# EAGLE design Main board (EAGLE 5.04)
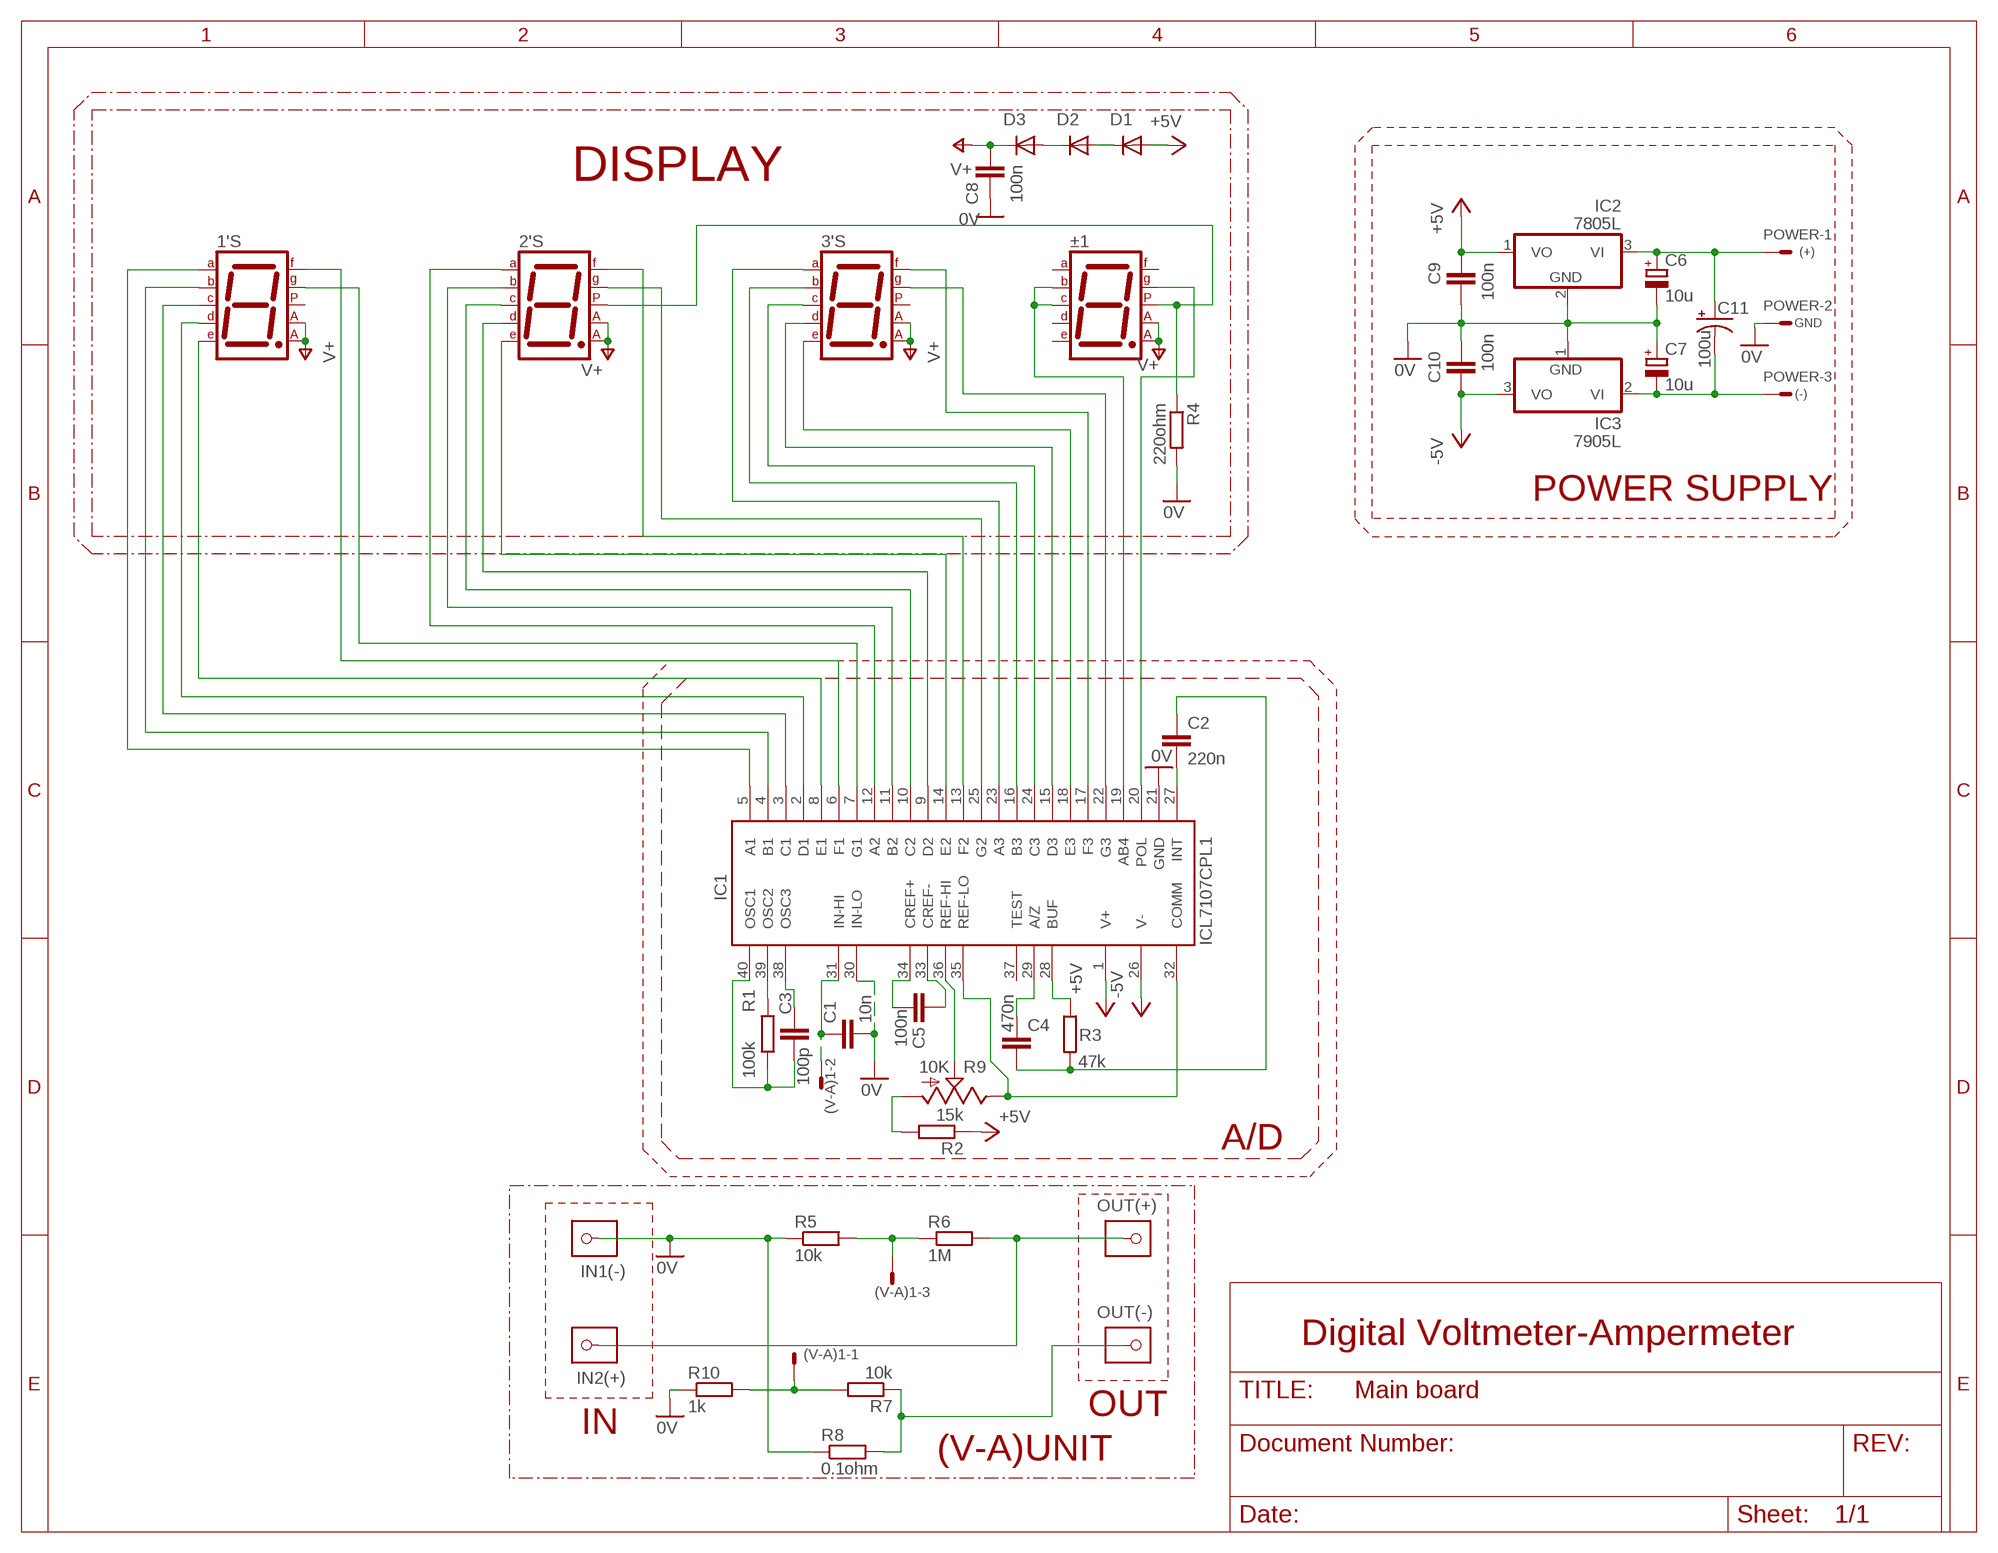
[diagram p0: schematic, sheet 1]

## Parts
1'S  7SEG-CA  [7SEG-13]
2'S  7SEG-CA  [7SEG-13]
3'S  7SEG-CA  [7SEG-13]
(V-A)1  22-27-2031-03  [6410-03]
C1  10n  C-EU050-025X075  [C050-025X075]
C2  220n  C-EU050-025X075  [C050-025X075]
C3  100p  C-EU050-025X075  [C050-025X075]
C4  470n  C-EU050-025X075  [C050-025X075]
C5  100n  C-EU050-025X075  [C050-025X075]
C6  10u  CPOL-EUE2.5-6  [E2,5-6]
C7  10u  CPOL-EUE2.5-6  [E2,5-6]
C8  100n  C-EU050-025X075  [C050-025X075]
C9  100n  C-EU050-025X075  [C050-025X075]
C10  100n  C-EU050-025X075  [C050-025X075]
C11  100u  CPOL-USE5-8.5  [E5-8,5]
D1  1N4148DO35-7  [DO35-7]
D2  1N4148DO35-7  [DO35-7]
D3  1N4148DO35-7  [DO35-7]
IC1  ICL7107CPL1  [DIL40]
IC2  7805L  [TO92]
IC3  7905L  [TO92]
IN1(-)  PINHEAD  [PINFOOT]
IN2(+)  PINHEAD  [PINFOOT]
OUT(+)  PINHEAD  [PINFOOT]
OUT(-)  PINHEAD  [PINFOOT]
POWER  22-27-2031-03  [6410-03]
R1  100k  R-EU_0207/10  [0207/10]
R2  15k  R-EU_0207/10  [0207/10]
R3  47k  R-EU_0207/10  [0207/10]
R4  220ohm  R-EU_0207/10  [0207/10]
R5  10k  R-EU_0207/10  [0207/10]
R6  1M  R-EU_0207/10  [0207/10]
R7  10k  R-EU_0207/10  [0207/10]
R8  0.1ohm  R-EU_0922/22  [0922/22]
R9  10K  TRIM_US-CA6V  [CA6V]
R10  1k  R-EU_0207/10  [0207/10]
±1  7SEG-CA  [7SEG-13]

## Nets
0V: C1.2 C6.- C7.+ C8.1 C9.1 C10.2 IC1.21(GND) IC1.30(IN-LO) IC2.2(GND) IC3.1(GND) IN1(-).P$1 POWER.2 R4.2 R5.1 R8.1 R10.1
+5V: C9.2 D1.A IC1.1(V+) IC2.1(VO) R2.1
-5V: C10.1 IC1.26(V-) IC3.3(VO)
N$1: 2'S.5(DP) R4.1 ±1.5(DP)
N$2: IC1.39(OSC2) R1.2
N$3: C7.- C11.- IC3.2(VI) POWER.3
N$4: C6.+ C11.+ IC2.3(VI) POWER.1
N$5: C3.1 IC1.38(OSC3)
N$6: (V-A)1.3 R5.2 R6.1
N$7: OUT(-).P$1 R7.1 R8.2
N$8: (V-A)1.1 R7.2 R10.2
N$9: C4.1 IC1.29(A/Z)
N$10: IC1.28(BUF) R3.1
N$11: C2.1 C4.2 R3.2
N$12: C2.2 IC1.27(INT)
N$13: C5.2 IC1.33(CREF-)
N$14: D2.C D3.A
N$15: D1.C D2.A
N$16: C5.1 IC1.34(CREF+)
N$17: C3.2 IC1.40(OSC1) R1.1
N$20: IC1.36(REF-HI) R9.S
N$21: IC1.32(COMM) IC1.35(REF-LO) R9.E
N$22: 3'S.10(G) IC1.22(G3)
N$23: 3'S.9(F) IC1.17(F3)
N$24: R2.2 R9.A
N$25: 3'S.1(E) IC1.18(E3)
N$26: 3'S.2(D) IC1.15(D3)
N$27: IC1.20(POL) ±1.10(G)
N$28: IC1.19(AB4) ±1.4(C) ±1.6(B)
N$29: 3'S.4(C) IC1.24(C3)
N$30: 3'S.6(B) IC1.16(B3)
N$31: 3'S.7(A) IC1.23(A3)
N$32: 2'S.10(G) IC1.25(G2)
N$33: 2'S.9(F) IC1.13(F2)
N$34: 2'S.1(E) IC1.14(E2)
N$35: 2'S.2(D) IC1.9(D2)
N$36: 2'S.4(C) IC1.10(C2)
N$37: 2'S.6(B) IC1.11(B2)
N$38: 2'S.7(A) IC1.12(A2)
N$39: 1'S.10(G) IC1.7(G1)
N$40: 1'S.9(F) IC1.6(F1)
N$41: 1'S.1(E) IC1.8(E1)
N$42: 1'S.2(D) IC1.2(D1)
N$43: 1'S.4(C) IC1.3(C1)
N$44: 1'S.6(B) IC1.4(B1)
N$45: 1'S.7(A) IC1.5(A1)
N$47: IN2(+).P$1 OUT(+).P$1 R6.2
N$48: (V-A)1.2 C1.1 IC1.31(IN-HI)
V+: 1'S.3(CA1) 1'S.8(CA2) 2'S.3(CA1) 2'S.8(CA2) 3'S.3(CA1) 3'S.8(CA2) C8.2 D3.C ±1.3(CA1) ±1.8(CA2)
Unconnected: 1'S.5(DP) 3'S.5(DP) IC1.37(TEST) ±1.1(E) ±1.2(D) ±1.7(A) ±1.9(F)

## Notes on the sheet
- DISPLAY
- (+)
- GND
- (-)
- POWER SUPPLY
- A/D
- Digital Voltmeter-Ampermeter
- OUT
- IN
- (V-A)UNIT

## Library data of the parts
1'S 2'S 3'S ±1 = special:7SEG-CA: 7-segment DISPLAY single anode, 13 mm
(V-A)1 POWER = con-molex:22-?-03: CONNECTOR wire to board 2.54 mm (.1 inch) pitch header
C1-C5 C8-C10 = resistor:C-EU: CAPACITOR, European symbol
C6 C7 = resistor:CPOL-EU: POLARIZED CAPACITOR, European symbol
C11 = rcl:CPOL-US: POLARIZED CAPACITOR, American symbol
D1-D3 = diode:1N4148: DIODE
IC1 = maxim-3:ICL7107CPL: LED DRIVER
IC2 = linear:78*: Positive VOLTAGE REGULATOR Source: http://cache.national.com/ds/LM/LM78L05.pdf http://www.fairchildsemi.com/ds/LM/LM7805.pdf
IC3 = linear:79*: Negative VOLTAGE REGULATOR
IN1(-) IN2(+) OUT(+) OUT(-) = my lib:PINHEAD
R1-R8 R10 = resistor:R-EU_: RESISTOR, European symbol
R9 = pot:TRIM_US-: POTENTIOMETER

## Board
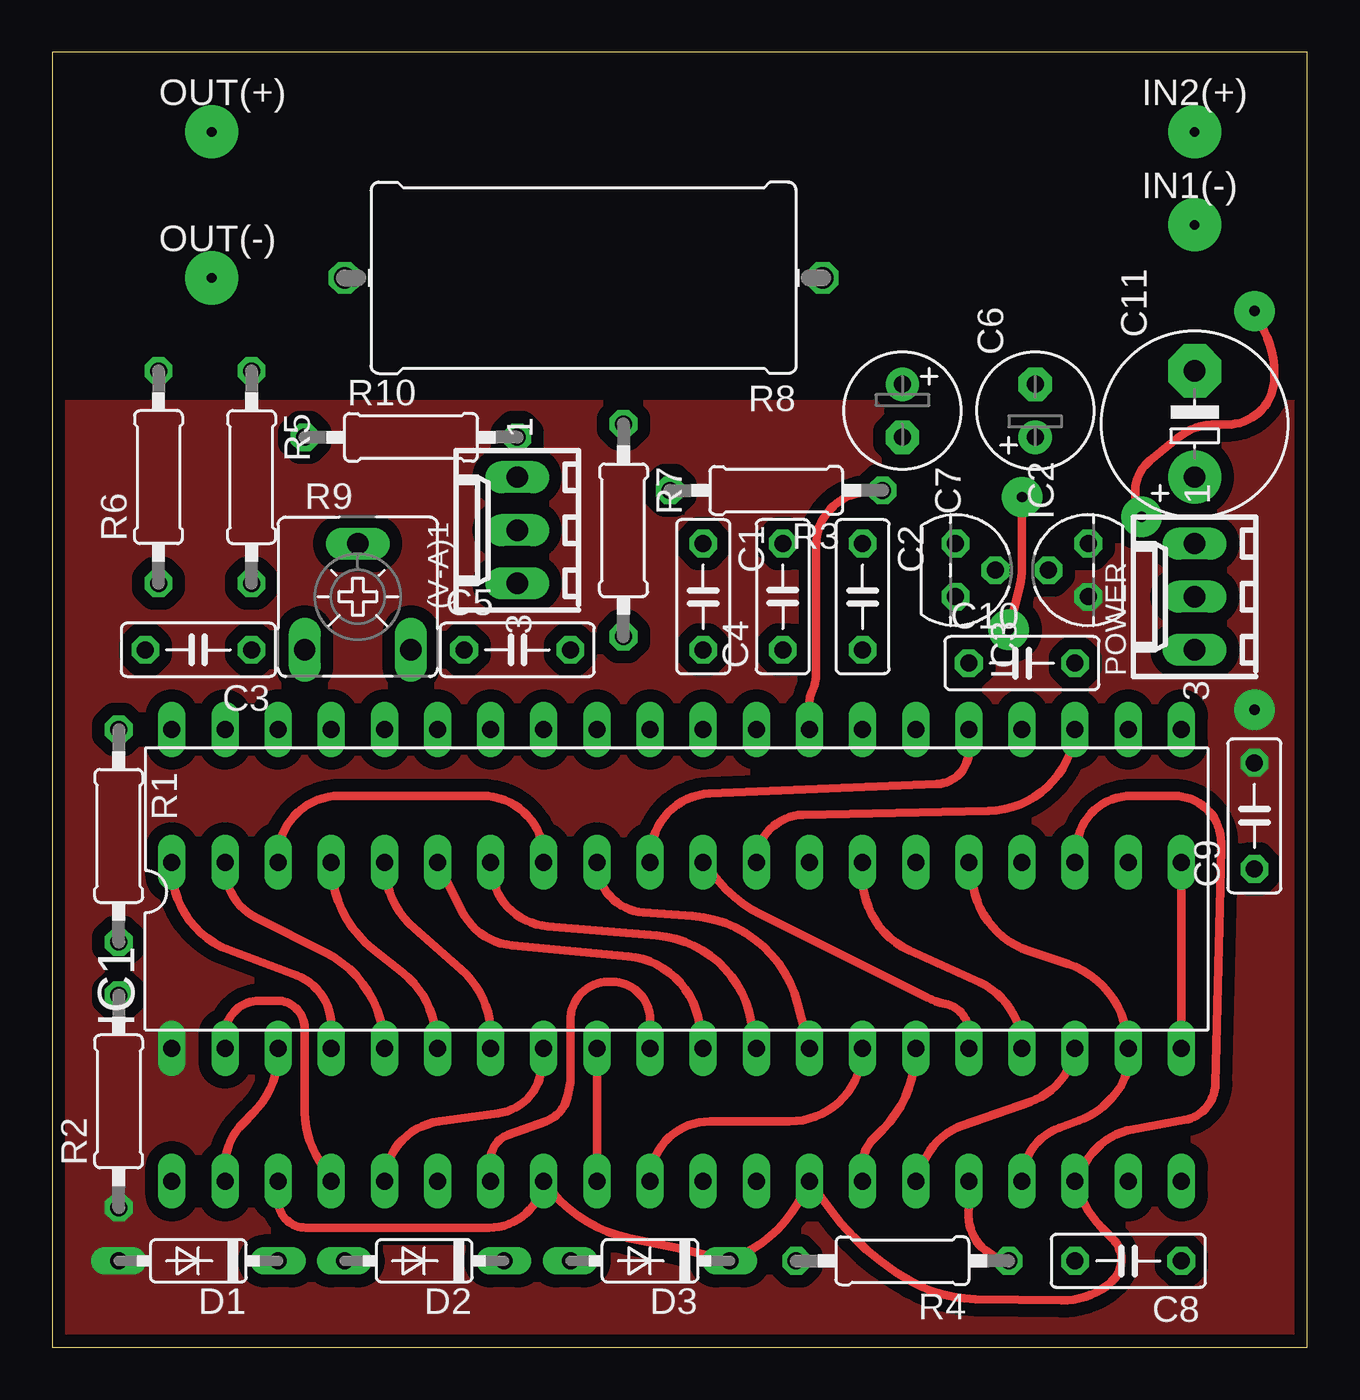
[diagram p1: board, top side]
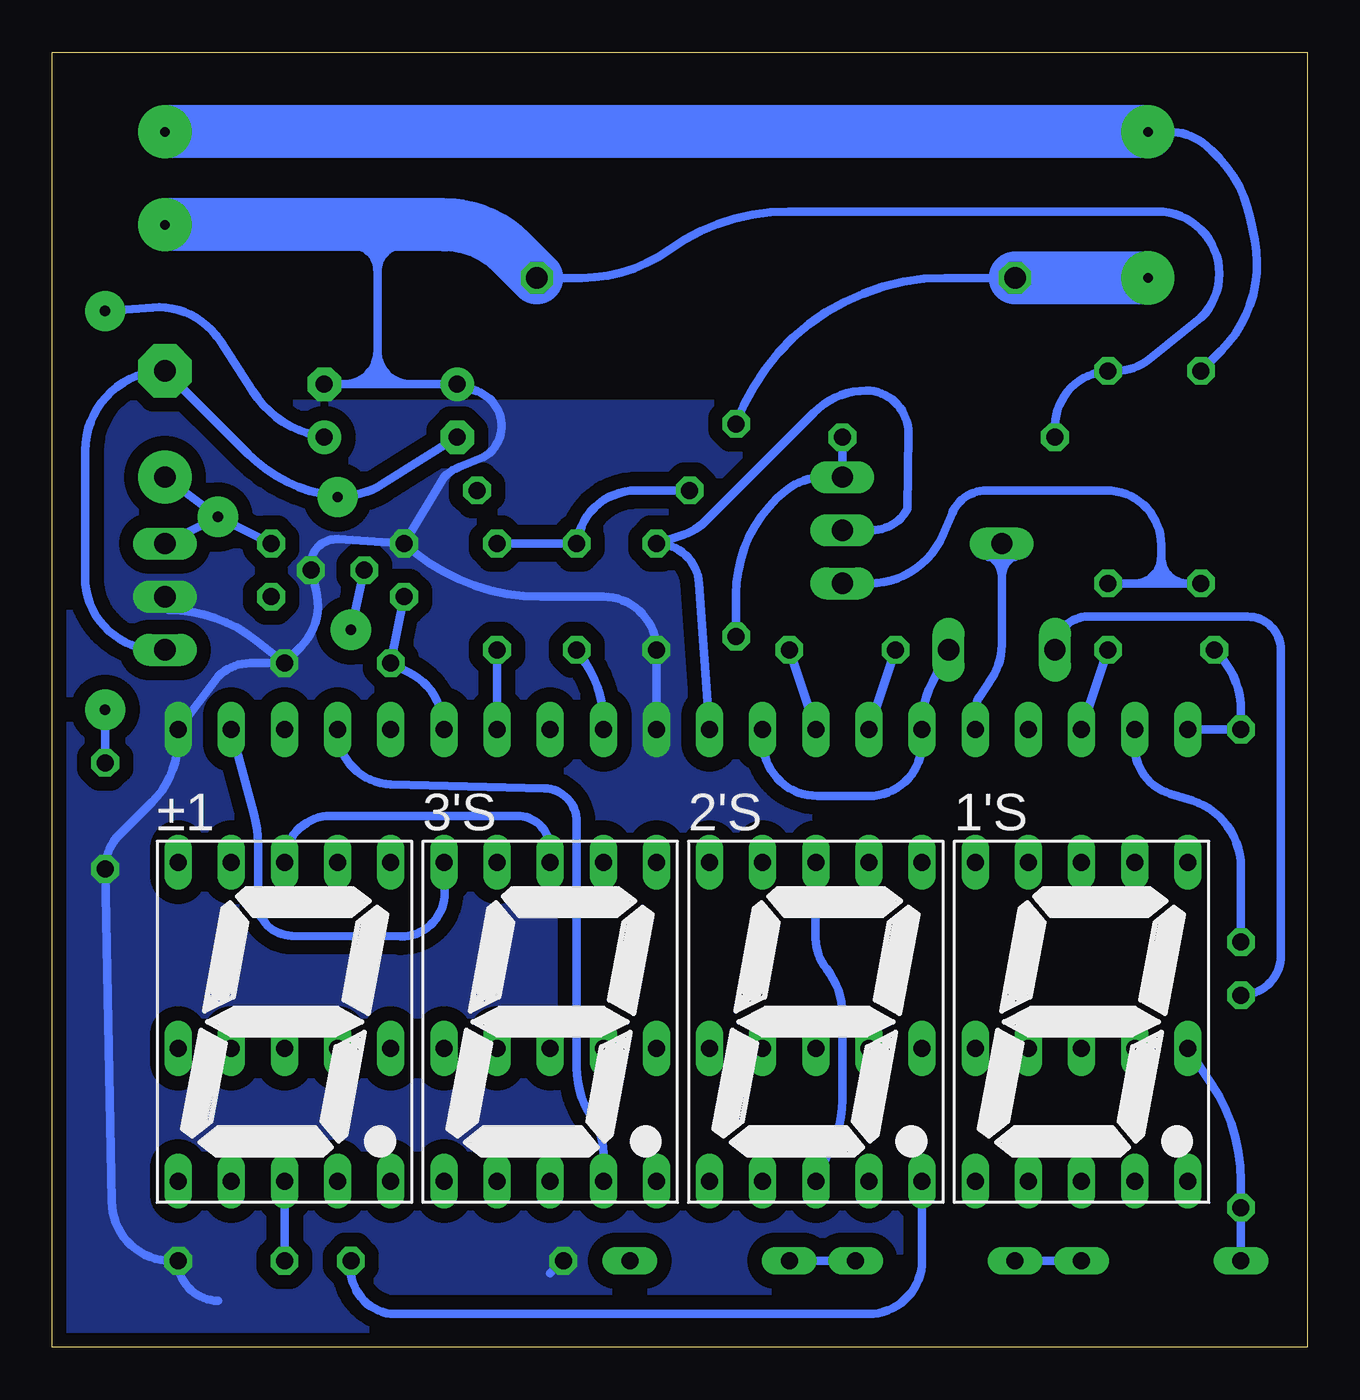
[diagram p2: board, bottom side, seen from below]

Size 59.99 x 61.9 mm. Coordinates in mm from the lower left corner, seen from the top.
Outline: 0,0 59.99,0 59.99,61.9 0,61.9 0,0
Copper layers (1*16): Top 0.035mm / dielectric 1.5mm / Bottom 0.035mm
Design rules "default *": minimum track width 16mil, minimum drill 10mil, track to track 10mil, track to pad 10mil, pad to pad 10mil, via to via 10mil, smd to smd 8mil, copper to edge 20mil, drill to drill 10mil, minimum pad ring 10mil, minimum via ring 8mil, stop-mask expansion 4mil, vias tented up to drill 0mil, thermal gap 10mil

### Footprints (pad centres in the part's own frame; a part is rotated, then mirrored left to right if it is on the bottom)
7SEG-13 = drill 0.813 long: 1 -5.08,-7.62; 2 -2.54,-7.62; 3 0,-7.62; 4 2.54,-7.62; 5 5.08,-7.62; 6 5.08,7.62; 7 2.54,7.62; 8 0,7.62; 9 -2.54,7.62; 10 -5.08,7.62
6410-03 = drill 1.016 long: 1 2.54,0; 2 0,0; 3 -2.54,0
C050-025X075 = drill 0.813 octagon: 1 -2.54,0; 2 2.54,0
E2,5-6 = drill 0.813 pad 1.6 round: + -1.27,0 | drill 0.813 pad 1.6 octagon: - 1.27,0
E5-8,5 = drill 1.016 pad 2.54 round: + -2.54,0 | drill 1.016 pad 2.54 octagon: - 2.54,0
DO35-7 = drill 0.813 long: A 3.81,0; C -3.81,0
DIL40 = drill 0.813 long: 1 -24.13,-7.62; 2 -21.59,-7.62; 3 -19.05,-7.62; 4 -16.51,-7.62; 5 -13.97,-7.62; 6 -11.43,-7.62; 7 -8.89,-7.62; 8 -6.35,-7.62; 9 -3.81,-7.62; 10 -1.27,-7.62; 11 1.27,-7.62; 12 3.81,-7.62; 13 6.35,-7.62; 14 8.89,-7.62; 15 11.43,-7.62; 16 13.97,-7.62; 17 16.51,-7.62; 18 19.05,-7.62; 19 21.59,-7.62; 20 24.13,-7.62; 21 24.13,7.62; 22 21.59,7.62; 23 19.05,7.62; 24 16.51,7.62; 25 13.97,7.62; 26 11.43,7.62; 27 8.89,7.62; 28 6.35,7.62; 29 3.81,7.62; 30 1.27,7.62; 31 -1.27,7.62; 32 -3.81,7.62; 33 -6.35,7.62; 34 -8.89,7.62; 35 -11.43,7.62; 36 -13.97,7.62; 37 -16.51,7.62; 38 -19.05,7.62; 39 -21.59,7.62; 40 -24.13,7.62
TO92 = drill 0.813 octagon: 1 -1.27,0; 2 0,1.905; 3 1.27,0
PINFOOT = drill 0.457 pad 2.54 round: P$1 0,0
0207/10 = drill 0.813 octagon: 1 -5.08,0; 2 5.08,0
0922/22 = drill 1.016 octagon: 1 -11.43,0; 2 11.43,0
CA6V = drill 1.016 long: A -2.54,-2.54; E 2.54,-2.54; S 0,2.54

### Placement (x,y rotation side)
1'S  10.79,15.56 0 bottom
2'S  23.5,15.56 0 bottom
3'S  36.2,15.56 0 bottom
(V-A)1  22.23,39.05 90 top
C1  31.11,35.88 270 top
C2  38.73,35.88 270 top
C3  6.99,33.34 180 top
C4  34.92,35.88 90 top
C5  22.23,33.34 0 top
C6  46.99,44.77 90 top
C7  40.64,44.77 270 top
C8  51.44,4.13 180 top
C9  57.47,25.4 90 top
C10  46.35,32.7 0 top
C11  54.61,44.13 90 top
D1  6.99,4.13 180 top
D2  17.78,4.13 180 top
D3  28.57,4.13 180 top
IC1  29.84,21.91 0 top
IC2  49.53,37.15 90 top
IC3  43.18,37.15 270 top
IN1(-)  54.61,53.66 0 top
IN2(+)  54.61,58.1 0 top
OUT(+)  7.62,58.1 0 top
OUT(-)  7.62,51.12 0 top
POWER  54.61,35.88 90 top
R1  3.17,24.45 270 top
R2  3.17,11.75 90 top
R3  34.61,40.96 180 top
R4  40.64,4.13 180 top
R5  9.53,41.59 270 top
R6  5.08,41.59 90 top
R7  27.3,39.05 270 top
R8  25.4,51.12 180 top
R9  14.61,35.88 0 top
R10  17.14,43.5 0 top
±1  48.9,15.56 0 bottom

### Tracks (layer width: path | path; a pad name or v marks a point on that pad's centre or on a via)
0V
  Bottom 0.406: 42.86,46.04 C7.+ 39.68,45.7 arc129 39.37,42.55 40.54,42.08 arc-23 41.27,41.59 IC3.1 | 44.45,46.04 42.86,46.04 | 44.45,46.04 46.04,46.04 | 46.04,46.04 C6.- | IC1.30 C1.2 arc-90 33.66,35.88 36.66,35.88 arc39 42.62,37.97 IC3.1 | C10.2 50.22,33.76 arc-39 54.44,35.24 POWER.2 | C10.2 48.13,33.47 arc-59 47.38,36.17 IC2.2 arc105 46.33,38.63 IC3.1 | 52.07,2.22 arc90 C8.1 54.29,4.13 arc90 57.15,6.99 C9.1 arc45 56.79,24.49 55.23,26.05 arc-45 53.98,29.07 IC1.21 52.07,32.07 arc45 50.54,32.7 C10.2 | R4.2 36.2,3.53 | R8.1 34.7,51.12 arc-36 30.5,52.47 arc36 24.8,54.29 7.18,54.29 arc135 5.08,49.21 7.56,47.23 arc39 9.15,46.67 R5.1 arc-90 12.06,43.81 R10.1 | 44.45,53.66 44.45,51.44 | 43.5,52.7 arc-90 44.45,51.75 44.45,51.44 | 44.45,51.44 arc-90 45.72,52.7 45.09,52.7 arc90 44.77,52.39 | 44.45,51.44 arc90 43.18,52.7 | 44.45,47.62 44.45,46.04 | 44.45,51.44 44.45,47.62 | 44.45,47.62 arc-90 42.86,46.04 | 44.45,47.62 arc90 46.04,46.04 | 46.04,46.04 45.09,46.04 arc-90 44.77,46.35 44.13,46.35
  Bottom 2.54: R8.1 38.05,52.34 arc-45 41.23,53.66 44.45,53.66 IN1(-).P$1
  pour Bottom (isolate 0.686, no thermals): 0,35.24 0.64,35.24 17.78,35.24 17.78,45.09 60.01,45.09 60.01,0 0,0
+5V  (via drill 0.5 pad 1.93)
  Bottom 0.406: D1.A R2.1 3.17,7.95 arc-34 4.58,12.58 IC1.1 | C9.2 v57.47,30.48
  pour Top (isolate 0.61, no thermals): 0,45.09 60.01,45.09 60.01,0 0,0
-5V
  Bottom 0.406: IC3.3 C10.1 42.98,32.28 arc63 IC1.26
N$1
  Top 0.406: ±1.5 43.81,6.67 arc90 R4.1
  Bottom 0.406: 2'S.5 18.41,4.15 arc90 20.98,1.59 43.81,1.59 arc90 R4.1
N$2
  Bottom 0.406: R1.2 3.17,22.96 arc-73 5.5,26.13 6.56,26.46 arc73 8.26,28.77 IC1.39
N$3  (via drill 0.5 pad 1.93)
  Top 0.406: v45.72,34.29 46.25,36.42 arc14 46.35,37.25 v46.35,40.64
  Bottom 0.406: POWER.3 arc90 58.42,36.51 58.42,42.86 arc90 C11.- 50.64,42.7 arc-33 47.11,40.8 v46.35,40.64 46.04,40.64 45.46,40.76 arc-20 44.22,41.26 C7.- | IC3.2 v45.72,34.29
N$4  (via drill 0.5 pad 1.93)
  Top 0.406: v57.47,49.53 57.95,48.57 arc-27 58.42,46.56 58.42,46.35 arc-91 56.15,44.11 55.68,44.12 arc40 53.78,43.45 52.47,42.38 arc84 52.09,39.82 v52.07,39.69
  Bottom 0.406: C6.+ arc49 50.43,45.7 51.98,48.12 arc-6 52.18,48.39 arc-56 55.2,49.7 v57.47,49.53 | IC2.3 v52.07,39.69 | v52.07,39.69 C11.+ | v52.07,39.69 POWER.1
N$5
  Bottom 0.406: IC1.38 C3.1
N$6
  Bottom 0.406: R6.1 5.71,36.51 | 6.99,36.51 7.62,36.51 | 8.26,36.51 7.62,36.51 | 8.26,36.51 R5.2 | (V-A)1.3 20.93,36.51 arc-67 17.43,38.82 16.98,39.87 arc67 15.33,40.96 9.6,40.96 arc90 6.99,38.34 6.99,37.15 | 5.71,36.51 arc90 6.99,37.78 arc90 8.26,36.51 | 5.71,36.51 6.35,36.51 | 6.35,36.51 6.99,36.51 | 6.99,36.51 6.99,37.15 | 6.35,36.51 6.99,37.15 | 6.99,37.15 7.62,36.51
N$7
  Bottom 0.406: R7.1 arc70 17.33,51.12 R8.2
  Bottom 2.54: OUT(-).P$1 R8.2
N$8
  Bottom 0.406: R7.2 27.3,36 arc51 24.92,40.96 arc39 23.12,41.59 (V-A)1.1 R10.2
N$9
  Bottom 0.406: C4.1 34.51,32.71 arc34 33.66,29.89 IC1.29
N$10
  Top 0.406: IC1.28 36.2,30.81 arc-27 36.33,31.39 arc27 36.51,32.15 36.51,38.32 arc-84 38.82,40.87 R3.1
N$11
  Bottom 0.406: C2.1 C4.2 34.92,38.44 arc83 32.07,40.96 R3.2
N$12
  Bottom 0.406: IC1.27 C2.2
N$13
  Bottom 0.406: IC1.33 C5.2
N$14
  Bottom 0.406: D2.C D3.A
N$15
  Bottom 0.406: D1.C D2.A
N$16
  Bottom 0.406: IC1.34 C5.1
N$17
  Bottom 0.406: IC1.40 R1.1 3.17,30.44 arc-45 4.33,33.22 C3.2
N$20
  Bottom 0.406: 14.61,36.51 R9.S | IC1.36 15.88,30.41 arc34 15.66,31.12 15.08,31.99 arc-34 14.61,33.56 14.61,36.51 | 14.61,37.15 arc90 13.97,37.78 arc-90 14.61,37.15 | 14.61,37.15 arc-90 15.24,37.78 | 14.61,36.51 14.61,37.15 | 14.61,36.51 14.61,36.83 | 14.61,36.83 arc90 13.49,37.94 13.65,37.94 13.65,38.1 | 14.61,36.51 14.61,36.83 | 14.61,36.83 arc-90 15.72,37.94
N$21
  Bottom 0.406: R9.E 17.93,31.76 arc-27 18.41,29.72 IC1.35 18.41,28.89 arc90 20.95,26.35 23.42,26.35 arc90 26.04,28.97 IC1.32
N$22
  Bottom 0.406: IC1.22 50.35,25.45 arc15 50.16,24.06 50.16,21.29 arc-90 48.56,19.67 43.35,19.63 arc-102 41.27,22.14 3'S.10
N$23
  Top 0.406: 3'S.9 38.73,22.46 arc65 40.97,18.98 44.34,17.44 arc-65 IC1.17
N$24
  Bottom 0.406: R9.A arc90 10.48,34.92 2.86,34.92 arc90 1.27,33.34 1.27,18.73 arc90 R2.2
N$25
  Top 0.406: IC1.18 arc-61 46.76,11.73 43.53,10.61 arc48 41.68,8.89 3'S.1
N$26
  Top 0.406: IC1.15 arc-49 39.36,10.07 arc49 38.73,8.69 3'S.2
N$27
  Top 0.406: IC1.20 ±1.10
N$28
  Top 0.406: ±1.6 44.03,22 arc61 46.69,18.94 48.55,18.32 arc-66 51.39,14.77 IC1.19 51.44,13.82 arc-45 50.65,11.91 50.4,11.67 arc-25 49.11,10.84 48.15,10.49 arc70 ±1.4
N$29
  Bottom 0.406: 3'S.4 33.66,9.29 arc-34 34.13,10.88 34.2,10.98 arc34 34.92,13.37 34.92,25.13 arc-88 36.47,26.71 43.82,26.91 arc88 IC1.24
N$30
  Top 0.406: 3'S.6 31.86,22.28 arc24 33.87,20.69 41.8,16.72 arc15 42.69,16.42 arc-79 43.81,15.05 IC1.16
N$31
  Top 0.406: 3'S.7 arc-89 35.88,25.45 44.76,25.64 arc84 IC1.23
N$32
  Top 0.406: IC1.25 43.81,28.51 arc-88 42.3,26.92 31.43,26.46 arc82 28.64,23.83 2'S.10
N$33
  Top 0.406: 2'S.9 arc86 28.25,20.79 30.6,20.62 arc-71 35.63,16.44 IC1.13
N$34
  Top 0.406: 2'S.1 arc-90 31.43,10.79 35.24,10.79 arc90 IC1.14
N$35
  Top 0.406: 2'S.2 IC1.9
N$36
  Top 0.406: 2'S.4 20.95,8.95 arc-70 21.79,10.15 23.61,10.81 arc59 24.62,11.99 24.77,12.7 24.77,15.77 arc-90 26.77,17.46 arc-90 28.57,15.66 IC1.10 28.57,14.96
N$37
  Top 0.406: 2'S.6 19.57,20.86 arc58 21.98,19.21 27.51,18.69 arc-76 30.93,15.47 IC1.11
N$38
  Top 0.406: 2'S.7 21.01,22.71 arc79 23.67,20.12 28.89,19.68 arc-75 33.41,15.61 IC1.12
N$39
  Top 0.406: 1'S.10 arc49 17.31,20.02 19.54,18.06 arc-49 20.95,14.95 IC1.7
N$40
  Top 0.406: 1'S.9 arc51 15.32,19.05 16.77,17.89 arc-44 18.31,15.14 IC1.6
N$41
  Top 0.406: 1'S.1 15.9,8.18 arc-75 18.49,10.79 21.31,11.18 arc76 23.39,13.3 IC1.8
N$42
  Top 0.406: 8.39,15.27 IC1.2 8.26,14.92 arc-90 9.9,16.57 10.74,16.57 arc-90 12.06,15.24 12.06,11.23 arc30 12.6,9.23 1'S.2
N$43
  Top 0.406: 1'S.4 8.26,8.63 arc-45 9.11,10.7 9.61,11.2 arc45 10.79,14.06 IC1.3
N$44
  Top 0.406: 1'S.6 5.71,22.96 arc63 8.08,19.14 11.68,17.77 arc-69 13.34,15.38 IC1.4
N$45
  Top 0.406: 1'S.7 8.26,22.96 arc63 9.77,20.52 13.04,18.88 arc-63 IC1.5
N$47
  Bottom 0.406: OUT(+).P$1 6.6,58.1 arc37 5.01,57.57 arc42 2.73,53.95 2.52,52.92 arc56 4.12,47.63 R6.2 | IN2(+).P$1 54.93,58.07
  Bottom 2.54: OUT(+).P$1 IN2(+).P$1
N$48
  Bottom 0.406: IC1.31 29.07,36.52 arc-86 C1.1 29.8,38.86 arc-27 28.77,39.49 23.57,44.69 arc45 21.09,45.73 arc90 19.07,43.68 19.11,40.06 arc60 20.85,39.05 (V-A)1.2
V+
  Top 0.406: 1'S.3 10.79,7.02 arc90 12.1,5.71 20.89,5.71 arc74 23.4,7.61 2'S.3 23.59,7.8 arc43 27.59,5.21 29.84,4.76 D3.C 33.02,4.45 arc37 35.88,7.3 3'S.3 37.15,6.63 arc25 41.09,3.12 arc28 44.14,2.3 48.23,2.24 arc42 50.63,3.13 arc93 50.69,5.19 50.18,5.7 arc-23 49.19,7.21 ±1.3 49.4,8.83 arc-50 51.67,10.43 54.12,10.86 arc79 55.6,12.58 55.88,23.81 55.88,24.11 arc90 53.63,26.35 51.58,26.35 arc84 48.98,23.99 ±1.8 | 1'S.8 10.79,23.43 arc-90 13.72,26.35 20.57,26.35 arc-90 23.5,23.43 | 2'S.8 23.5,23.43 | 23.5,23.43 23.54,23.18
  Bottom 0.406: ±1.3 C8.2 | ±1.8 arc90 46.67,25.4 37.78,25.4 arc90 36.2,23.81 3'S.8 | 2'S.3 22.64,9.87 arc-24 22.23,11.81 22.23,15.91 arc-39 22.99,18.11 arc38 23.5,19.53 2'S.8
